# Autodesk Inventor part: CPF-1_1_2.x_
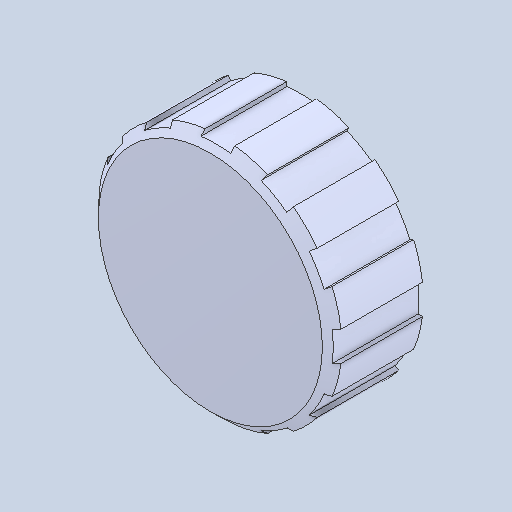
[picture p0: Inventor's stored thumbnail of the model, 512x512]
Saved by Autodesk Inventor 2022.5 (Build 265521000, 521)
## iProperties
Created: 2024-09
Part Number: CPF-1_1_2.x_
Material: 一般
Document SubType Name: Modeling
Designer: ImaoCorp
Density: 1 g/cm^3
Appearance: 既定
Author: ImaoCorp
Sending System: SOLIDWORKS 2022-2022290
MC: AMD64
MC_MODEL: Intel64 Family 6 Model 60 Stepping 3, GenuineIntel
OS: Windows_NT
FRU: Parasolid Version 33.1, build 260,  4-25-2022
FORMAT: text
GUISE: transmit
KEY: FILECPF-1_1_2.x_t
DATE: Tue Sep  3 09:28:58 2024
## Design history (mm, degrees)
feature "Base1"
node "ソリッド1"
